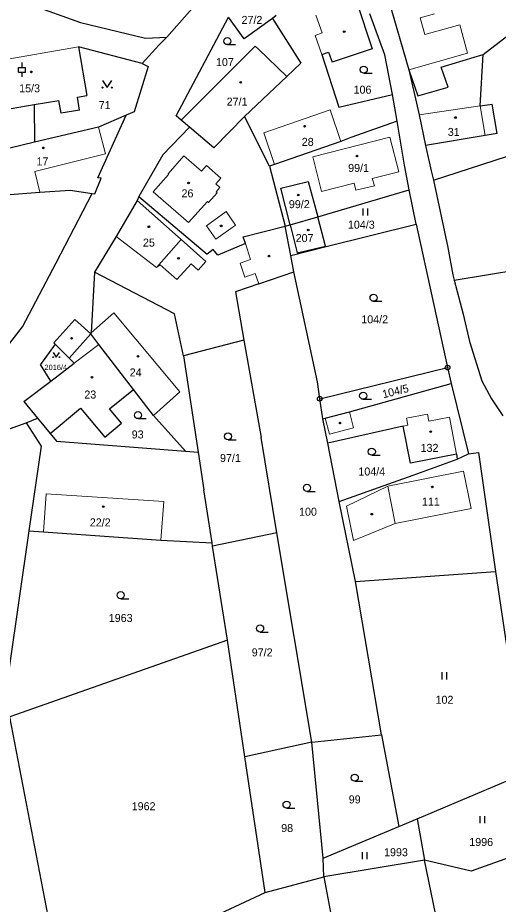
# Model space of a CAD drawing. Extents: x -820420 to -815896, y -1105820 to -1103643.
# Drawn here: x -817711.7 to -817609.6, y -1105107.9 to -1104919.6 of the extents above; entities that cross this region are included whole.
import ezdxf
from ezdxf.enums import TextEntityAlignment as Align

# ---------------------------------------------------------------- set-up
doc = ezdxf.new("R2010")
doc.units = 0
doc.header["$LTSCALE"] = 0.68
for name, color, linetype, lineweight in [('1', 7, 'Continuous', 25), ('3', 7, 'Continuous', 25), ('4', 7, 'Continuous', 13), ('5', 7, 'Continuous', 25), ('8', 7, 'Continuous', 25)]:
    doc.layers.add(name, color=color, linetype=linetype, lineweight=lineweight)
doc.layers.add('2', color=7, linetype='Continuous')

msp = doc.modelspace()

# ---------------------------------------------------------------- linework, layer by layer
at = {"layer": '1'}
for p, q in [((-817635.6, -1104906.5), (-817628.62, -1104930.65)), ((-817709.05, -1104916.79), (-817698.32, -1104920.58)), ((-817639.74, -1104916.15), (-817636.38, -1104926.16)), ((-817633.72, -1104927.48), (-817636.91, -1104918.76)), ((-817698.32, -1104920.58), (-817684.56, -1104923.92)), ((-817678.03, -1104940.45), (-817666.94, -1104919.46)), ((-817663.6, -1104924.08), (-817666.94, -1104919.46)), ((-817657.59, -1104919.72), (-817663.6, -1104924.08)), ((-817656.77, -1104919.13), (-817657.59, -1104919.72)), ((-817657.59, -1104919.72), (-817651.54, -1104929.22)), ((-817612.83, -1104927.36), (-817605.73, -1104921.95)), ((-817684.56, -1104923.92), (-817680.01, -1104923.68)), ((-817680.01, -1104923.68), (-817681.72, -1104925.42)), ((-817698.72, -1104925.76), (-817697, -1104936.12)), ((-817685.27, -1104929.28), (-817698.72, -1104925.76)), ((-817681.72, -1104925.42), (-817685.27, -1104929.28)), ((-817676.94, -1104941.36), (-817661.28, -1104925.6)), ((-817661.28, -1104925.6), (-817660.56, -1104926.25)), ((-817660.56, -1104926.25), (-817654.55, -1104932.07)), ((-817636.38, -1104926.16), (-817644.89, -1104929.02)), ((-817647.06, -1104927.4), (-817645.65, -1104926.9)), ((-817647.06, -1104927.4), (-817643.48, -1104938.56)), ((-817645.65, -1104926.9), (-817644.89, -1104929.02)), ((-817632.11, -1104935.86), (-817633.72, -1104927.48)), ((-817621.79, -1104930.11), (-817614.72, -1104927.93)), ((-817614.72, -1104927.93), (-817612.83, -1104927.36)), ((-817613.49, -1104938.27), (-817612.83, -1104927.36)), ((-817683.99, -1104929.96), (-817686.94, -1104939.54)), ((-817685.27, -1104929.28), (-817683.99, -1104929.96)), ((-817654.55, -1104932.07), (-817651.54, -1104929.22)), ((-817620.3, -1104934.31), (-817621.79, -1104930.11)), ((-817663.51, -1104940.56), (-817654.55, -1104932.07)), ((-817628.62, -1104930.65), (-817626.45, -1104940.24)), ((-817628.62, -1104930.65), (-817626.71, -1104936.18)), ((-817643.48, -1104938.56), (-817632.11, -1104935.86)), ((-817631.08, -1104941.53), (-817632.11, -1104935.86)), ((-817626.71, -1104936.18), (-817620.3, -1104934.31)), ((-817708.14, -1104938.03), (-817702.91, -1104937.13)), ((-817702.46, -1104939.87), (-817702.91, -1104937.13)), ((-817698.98, -1104936.46), (-817697, -1104936.12)), ((-817698.51, -1104939.18), (-817698.98, -1104936.46)), ((-817713.03, -1104938.87), (-817708.14, -1104938.03)), ((-817708.14, -1104938.03), (-817708.08, -1104946.04)), ((-817698.51, -1104939.18), (-817702.46, -1104939.87)), ((-817686.94, -1104939.54), (-817688.64, -1104940.27)), ((-817613.49, -1104938.27), (-817610.9, -1104937.92)), ((-817609.86, -1104944.17), (-817610.9, -1104937.92)), ((-817694.66, -1104953.6), (-817688.64, -1104940.27)), ((-817688.64, -1104940.27), (-817694.54, -1104942.82)), ((-817676.94, -1104941.36), (-817678.03, -1104940.45)), ((-817675.22, -1104942.8), (-817676.94, -1104941.36)), ((-817663.51, -1104940.56), (-817670.03, -1104947.24)), ((-817658.22, -1104951.1), (-817663.51, -1104940.56)), ((-817631.08, -1104941.53), (-817640.9, -1104945.04)), ((-817629.55, -1104950.9), (-817631.08, -1104941.53)), ((-817626.45, -1104940.24), (-817625.09, -1104946.72)), ((-817694.54, -1104942.82), (-817708.08, -1104946.04)), ((-817680.82, -1104948.67), (-817675.22, -1104942.8)), ((-817670.03, -1104947.24), (-817675.22, -1104942.8)), ((-817640.9, -1104945.04), (-817643.03, -1104945.89)), ((-817612.44, -1104944.57), (-817625.09, -1104946.72)), ((-817609.86, -1104944.17), (-817612.44, -1104944.57)), ((-817708.08, -1104946.04), (-817716.9, -1104948.13)), ((-817643.03, -1104945.89), (-817657.12, -1104950.74)), ((-817625.09, -1104946.72), (-817623.86, -1104952.1)), ((-817623.38, -1104954.07), (-817599.07, -1104946.21)), ((-817680.82, -1104948.67), (-817685.92, -1104957.55)), ((-817657.12, -1104950.74), (-817658.22, -1104951.1)), ((-817628.57, -1104956.14), (-817629.55, -1104950.9)), ((-817658.22, -1104951.1), (-817654.86, -1104963.88)), ((-817623.86, -1104952.1), (-817623.38, -1104954.07)), ((-817695.3, -1104957.01), (-817693.97, -1104953.69)), ((-817693.97, -1104953.69), (-817694.66, -1104953.6)), ((-817655.79, -1104955.8), (-817649.96, -1104954.4)), ((-817649.96, -1104954.4), (-817647.97, -1104961.85)), ((-817623.38, -1104954.07), (-817620.31, -1104968.4)), ((-817714.27, -1104957.17), (-817706.93, -1104956.61)), ((-817706.93, -1104956.61), (-817700.49, -1104956.19)), ((-817700.49, -1104956.19), (-817695.82, -1104956.94)), ((-817653.85, -1104963.58), (-817655.79, -1104955.8)), ((-817647.97, -1104961.85), (-817628.57, -1104956.14)), ((-817627.09, -1104963.44), (-817628.57, -1104956.14)), ((-817703.49, -1104971.65), (-817695.82, -1104956.94)), ((-817695.82, -1104956.94), (-817695.3, -1104957.01)), ((-817686.31, -1104958.41), (-817690.73, -1104966.04)), ((-817685.92, -1104957.55), (-817686.31, -1104958.41)), ((-817685.92, -1104957.55), (-817671.45, -1104969.83)), ((-817653.85, -1104963.58), (-817647.97, -1104961.85)), ((-817663.77, -1104966.09), (-817654.86, -1104963.88)), ((-817654.86, -1104963.88), (-817653.85, -1104963.58)), ((-817653.67, -1104970.08), (-817654.86, -1104963.88)), ((-817646.15, -1104968.19), (-817627.09, -1104963.44)), ((-817627.09, -1104963.44), (-817620.39, -1104993.9)), ((-817690.73, -1104966.04), (-817695.38, -1104973.64)), ((-817663.33, -1104967.57), (-817669.19, -1104969.98)), ((-817663.33, -1104967.57), (-817663.77, -1104966.09)), ((-817670.13, -1104968.8), (-817671.45, -1104969.83)), ((-817669.19, -1104969.98), (-817670.13, -1104968.8)), ((-817653.67, -1104970.08), (-817646.15, -1104968.19)), ((-817620.31, -1104968.4), (-817619.28, -1104974.19)), ((-817710.66, -1104985.25), (-817703.49, -1104971.65)), ((-817653.03, -1104973.58), (-817653.67, -1104970.08)), ((-817619.02, -1104975.33), (-817593.46, -1104971.11)), ((-817660.5, -1104976.07), (-817653.03, -1104973.58)), ((-817648.02, -1104996.92), (-817653.03, -1104973.58)), ((-817695.38, -1104973.64), (-817696.05, -1104986.5)), ((-817678.4, -1104982.48), (-817695.38, -1104973.64)), ((-817619.28, -1104974.19), (-817619.02, -1104975.33)), ((-817619.02, -1104975.33), (-817617.11, -1104982.53)), ((-817660.5, -1104976.07), (-817665.45, -1104977.81)), ((-817665.45, -1104977.81), (-817663.63, -1104988.09)), ((-817676.45, -1104991.42), (-817678.4, -1104982.48)), ((-817617.11, -1104982.53), (-817615.71, -1104988.33)), ((-817704, -1104988.65), (-817699.56, -1104983.68)), ((-817696.17, -1104986.71), (-817699.56, -1104983.68)), ((-817714.53, -1104990.23), (-817710.66, -1104985.25)), ((-817696.05, -1104986.5), (-817696.17, -1104986.71)), ((-817694.45, -1104989), (-817696.17, -1104986.71)), ((-817704, -1104988.65), (-817703.72, -1104988.93)), ((-817663.63, -1104988.09), (-817676.45, -1104991.42)), ((-817663.63, -1104988.09), (-817659.99, -1105008.72)), ((-817615.71, -1104988.33), (-817613.13, -1104996.68)), ((-817703.72, -1104988.93), (-817706.82, -1104993.26)), ((-817703.72, -1104988.93), (-817700.73, -1104991.87)), ((-817687.07, -1104998.54), (-817694.45, -1104989)), ((-817700.73, -1104991.87), (-817699.65, -1104992.96)), ((-817676.45, -1104991.42), (-817673.36, -1105011.84)), ((-817704.62, -1104996.77), (-817706.82, -1104993.26)), ((-817704.62, -1104996.77), (-817699.65, -1104992.96)), ((-817647.52, -1105000.5), (-817620.39, -1104993.9)), ((-817620.39, -1104993.9), (-817619.66, -1104997.26)), ((-817710.39, -1105001.11), (-817704.62, -1104996.77)), ((-817647.52, -1105000.5), (-817648.02, -1104996.92)), ((-817641.25, -1105003.28), (-817619.66, -1104997.26)), ((-817619.66, -1104997.26), (-817615.95, -1105012.22)), ((-817613.13, -1104996.68), (-817611.07, -1105000.53)), ((-817692.17, -1105002.66), (-817687.07, -1104998.54)), ((-817682.83, -1105004.06), (-817687.07, -1104998.54)), ((-817710.39, -1105001.11), (-817707.45, -1105004.65)), ((-817646.87, -1105004.76), (-817647.52, -1105000.5)), ((-817611.07, -1105000.53), (-817608.63, -1105004.11)), ((-817704.77, -1105007.88), (-817698.33, -1105002.54)), ((-817698.33, -1105002.54), (-817693.18, -1105008.68)), ((-817689.65, -1105005.71), (-817692.17, -1105002.66)), ((-817646.36, -1105004.63), (-817641.25, -1105003.28)), ((-817720.13, -1105009.32), (-817709.86, -1105005.6)), ((-817709.86, -1105005.6), (-817706.69, -1105010.56)), ((-817682.83, -1105004.06), (-817676.02, -1105011.65)), ((-817646.87, -1105004.76), (-817646.36, -1105004.63)), ((-817645.84, -1105009.94), (-817646.87, -1105004.76)), ((-817693.18, -1105008.68), (-817689.65, -1105005.71)), ((-817629.79, -1105006.31), (-817645.84, -1105009.94)), ((-817628.28, -1105014.17), (-817629.79, -1105006.31)), ((-817704.77, -1105007.88), (-817703.44, -1105009.49)), ((-817656.62, -1105029.01), (-817659.99, -1105008.72)), ((-817706.69, -1105010.56), (-817709.27, -1105028.56)), ((-817703.44, -1105009.49), (-817676.02, -1105011.65)), ((-817643.38, -1105022.33), (-817645.84, -1105009.94)), ((-817676.02, -1105011.65), (-817673.36, -1105011.84)), ((-817673.36, -1105011.84), (-817672.17, -1105019.85)), ((-817618.52, -1105012.29), (-817628.28, -1105014.17)), ((-817618.52, -1105012.29), (-817618.34, -1105013.32)), ((-817618.34, -1105013.32), (-817615.95, -1105012.22)), ((-817615.95, -1105012.22), (-817613.81, -1105011.94)), ((-817613.81, -1105011.94), (-817610.21, -1105037.23)), ((-817627.69, -1105016.77), (-817618.34, -1105013.32)), ((-817643.38, -1105022.33), (-817627.69, -1105016.77)), ((-817670.36, -1105031.11), (-817672.17, -1105019.85)), ((-817639.96, -1105039.33), (-817643.38, -1105022.33)), ((-817709.27, -1105028.56), (-817713.48, -1105057.68)), ((-817709.27, -1105028.56), (-817706.17, -1105028.76)), ((-817706.17, -1105028.76), (-817681.24, -1105030.52)), ((-817656.62, -1105029.01), (-817670.27, -1105031.86)), ((-817649.25, -1105073.45), (-817656.62, -1105029.01)), ((-817681.24, -1105030.52), (-817670.36, -1105031.11)), ((-817670.27, -1105031.86), (-817670.36, -1105031.11)), ((-817667.12, -1105051.76), (-817670.27, -1105031.86)), ((-817639.96, -1105039.33), (-817610.21, -1105037.23)), ((-817610.21, -1105037.23), (-817603.91, -1105080)), ((-817634.41, -1105071.9), (-817639.96, -1105039.33)), ((-817667.12, -1105051.76), (-817713.36, -1105068.05)), ((-817663.43, -1105076.57), (-817667.12, -1105051.76)), ((-817702.55, -1105124.25), (-817713.36, -1105068.05)), ((-817649.25, -1105073.45), (-817634.41, -1105071.9)), ((-817634.41, -1105071.9), (-817630.76, -1105091.4)), ((-817649.25, -1105073.45), (-817663.43, -1105076.57)), ((-817646.79, -1105098.13), (-817649.25, -1105073.45)), ((-817659.14, -1105105.4), (-817663.43, -1105076.57)), ((-817626.88, -1105089.77), (-817603.91, -1105080)), ((-817630.76, -1105091.4), (-817626.88, -1105089.77)), ((-817626.88, -1105089.77), (-817625.33, -1105098.49)), ((-817646.79, -1105098.13), (-817630.76, -1105091.4)), ((-817603.17, -1105096.45), (-817615.37, -1105100.88)), ((-817646.66, -1105102.08), (-817646.79, -1105098.13)), ((-817625.33, -1105098.49), (-817646.66, -1105102.08)), ((-817612.44, -1105160.35), (-817625.33, -1105098.49)), ((-817615.37, -1105100.88), (-817625.33, -1105098.49)), ((-817646.66, -1105102.08), (-817625.51, -1105215.45))]:
    msp.add_line(p, q, dxfattribs=at)
for points in [[(-817693.08, -1104912.51), (-817671.42, -1104913.92), (-817680.01, -1104923.68)], [(-817653.85, -1104963.58), (-817652.36, -1104969.52), (-817646.31, -1104968.07), (-817647.97, -1104961.85)], [(-817709.86, -1105005.6), (-817707.45, -1105004.65), (-817704.77, -1105007.88)], [(-817669.74, -1105110.38), (-817659.14, -1105105.4), (-817646.66, -1105102.08)]]:
    msp.add_lwpolyline(points, dxfattribs=at)
at = {"layer": '3'}
for p, q in [((-817667.153, -1104925.29), (-817665.403, -1104925.29)), ((-817711.481, -1104930.121), (-817709.979, -1104930.121)), ((-817711.481, -1104931.122), (-817711.481, -1104930.121)), ((-817710.73, -1104930.121), (-817710.73, -1104929.12)), ((-817709.979, -1104931.122), (-817709.979, -1104930.121)), ((-817711.481, -1104931.122), (-817709.979, -1104931.122)), ((-817710.73, -1104932.12), (-817710.73, -1104931.122)), ((-817638.183, -1104931.36), (-817636.433, -1104931.36)), ((-817638.331, -1104961.61), (-817638.331, -1104960.11)), ((-817637.33, -1104961.61), (-817637.33, -1104960.11)), ((-817636.113, -1104979.81), (-817634.363, -1104979.81)), ((-817638.313, -1105000.63), (-817636.563, -1105000.63)), ((-817686.113, -1105004.74), (-817684.363, -1105004.74)), ((-817667.013, -1105009.25), (-817665.263, -1105009.25)), ((-817636.483, -1105012.51), (-817634.733, -1105012.51)), ((-817650.243, -1105020.18), (-817648.493, -1105020.18)), ((-817689.793, -1105042.99), (-817688.043, -1105042.99)), ((-817660.203, -1105050.06), (-817658.453, -1105050.06)), ((-817621.561, -1105060.12), (-817621.561, -1105058.62)), ((-817620.56, -1105060.12), (-817620.56, -1105058.62)), ((-817640.103, -1105081.74), (-817638.353, -1105081.74)), ((-817654.583, -1105087.47), (-817652.833, -1105087.47)), ((-817613.501, -1105090.67), (-817613.501, -1105089.17)), ((-817612.5, -1105090.67), (-817612.5, -1105089.17)), ((-817638.461, -1105098.3), (-817638.461, -1105096.8)), ((-817637.46, -1105098.3), (-817637.46, -1105096.8))]:
    msp.add_line(p, q, dxfattribs=at)
for points in [[(-817693.69, -1104932.929), (-817692.69, -1104934.43), (-817691.69, -1104932.929)], [(-817704.13, -1104990.654), (-817703.46, -1104991.66), (-817702.79, -1104990.654)]]:
    msp.add_lwpolyline(points, dxfattribs=at)
for centre, radius in [((-817667.1529, -1104924.5398), 0.75), ((-817638.1829, -1104930.6098), 0.75), ((-817693.69, -1104934.4295), 0.1), ((-817691.69, -1104934.4295), 0.1), ((-817636.1129, -1104979.0598), 0.75), ((-817704.13, -1104991.6596), 0.067), ((-817702.79, -1104991.6596), 0.067), ((-817638.3129, -1104999.8798), 0.75), ((-817686.1129, -1105003.9898), 0.75), ((-817667.0129, -1105008.4998), 0.75), ((-817636.4829, -1105011.7598), 0.75), ((-817650.2429, -1105019.4298), 0.75), ((-817689.7929, -1105042.2398), 0.75), ((-817660.2029, -1105049.3098), 0.75), ((-817640.1029, -1105080.9898), 0.75), ((-817654.5829, -1105086.7198), 0.75)]:
    msp.add_circle(centre, radius, dxfattribs=at)
at = {"layer": '4'}
for p, q in [((-817648.4, -1104919), (-817647.04, -1104922.82)), ((-817623.18, -1104918.75), (-817626.2, -1104919.58)), ((-817626.2, -1104919.58), (-817625.22, -1104923.13)), ((-817625.22, -1104923.13), (-817617.82, -1104921.1)), ((-817617.82, -1104921.1), (-817616.16, -1104927.13)), ((-817647.04, -1104922.82), (-817648.5, -1104923.34)), ((-817648.5, -1104923.34), (-817647.06, -1104927.4)), ((-817698.72, -1104925.76), (-817724.12, -1104930.13)), ((-817616.16, -1104927.13), (-817628.62, -1104930.65)), ((-817626.45, -1104940.24), (-817613.49, -1104938.27)), ((-817613.49, -1104938.27), (-817612.44, -1104944.57)), ((-817693.05, -1104948.51), (-817694.54, -1104942.82)), ((-817657.12, -1104950.74), (-817659.42, -1104944.06)), ((-817632.68, -1104944.93), (-817649.02, -1104949.11)), ((-817630.77, -1104952.28), (-817632.68, -1104944.93)), ((-817679.74, -1104952.75), (-817676.36, -1104948.93)), ((-817676.36, -1104948.93), (-817672.66, -1104952.16)), ((-817649.02, -1104949.11), (-817647.13, -1104956.47)), ((-817672.66, -1104952.16), (-817671.6, -1104950.96)), ((-817671.6, -1104950.96), (-817668.51, -1104953.67)), ((-817682.9, -1104956.56), (-817679.62, -1104952.86)), ((-817679.62, -1104952.86), (-817679.74, -1104952.75)), ((-817668.51, -1104953.67), (-817669.57, -1104954.87)), ((-817675.39, -1104963.11), (-817682.9, -1104956.56)), ((-817669.57, -1104954.87), (-817668.73, -1104955.61)), ((-817668.73, -1104955.61), (-817669.54, -1104956.53)), ((-817669.54, -1104956.53), (-817669.31, -1104956.74)), ((-817686.31, -1104958.41), (-817676.95, -1104966.69)), ((-817669.31, -1104956.74), (-817671.18, -1104958.81)), ((-817671.39, -1104958.63), (-817675.39, -1104963.11)), ((-817671.18, -1104958.81), (-817671.39, -1104958.63)), ((-817671.59, -1104963.76), (-817667.38, -1104960.77)), ((-817667.38, -1104960.77), (-817665.4, -1104963.65)), ((-817669.61, -1104966.63), (-817671.59, -1104963.76)), ((-817665.4, -1104963.65), (-817669.61, -1104966.63)), ((-817682.19, -1104972.62), (-817690.73, -1104966.04)), ((-817676.95, -1104966.69), (-817682.19, -1104972.62)), ((-817676.95, -1104966.69), (-817671.7, -1104971.33)), ((-817662.21, -1104970.93), (-817663.33, -1104967.57)), ((-817671.7, -1104971.33), (-817673.33, -1104973.17)), ((-817664.45, -1104971.68), (-817662.21, -1104970.93)), ((-817663.46, -1104974.67), (-817664.45, -1104971.68)), ((-817681.43, -1104972.05), (-817682.19, -1104972.62)), ((-817677.86, -1104975.21), (-817681.43, -1104972.05)), ((-817674.86, -1104971.82), (-817677.86, -1104975.21)), ((-817673.33, -1104973.17), (-817674.86, -1104971.82)), ((-817661.22, -1104973.92), (-817663.46, -1104974.67)), ((-817660.5, -1104976.07), (-817661.22, -1104973.92)), ((-817696.05, -1104986.5), (-817691.24, -1104982.28)), ((-817691.24, -1104982.28), (-817677.26, -1104999.01)), ((-817700.73, -1104991.87), (-817696.17, -1104986.71)), ((-817699.65, -1104992.96), (-817694.45, -1104989)), ((-817677.26, -1104999.01), (-817682.83, -1105004.06)), ((-817641.25, -1105003.28), (-817640.36, -1105006.66)), ((-817645.47, -1105008.01), (-817646.36, -1105004.63)), ((-817629.09, -1105004.66), (-817624.64, -1105003.76)), ((-817628.81, -1105006.12), (-817629.09, -1105004.66)), ((-817624.64, -1105003.76), (-817624.36, -1105005.26)), ((-817624.36, -1105005.26), (-817620, -1105004.44)), ((-817620, -1105004.44), (-817618.52, -1105012.29)), ((-817640.36, -1105006.66), (-817645.47, -1105008.01)), ((-817629.79, -1105006.31), (-817628.81, -1105006.12)), ((-817633.1, -1105019.1), (-817616.98, -1105015.89)), ((-817616.98, -1105015.89), (-817615.39, -1105023.85)), ((-817706.17, -1105028.76), (-817705.6, -1105020.69)), ((-817705.6, -1105020.69), (-817680.64, -1105022.33)), ((-817641.82, -1105023.32), (-817633.1, -1105019.1)), ((-817631.52, -1105027.04), (-817633.1, -1105019.1)), ((-817681.24, -1105030.52), (-817680.64, -1105022.33)), ((-817640.4, -1105030.63), (-817641.82, -1105023.32)), ((-817615.39, -1105023.85), (-817631.52, -1105027.04)), ((-817631.52, -1105027.04), (-817640.4, -1105030.63))]:
    msp.add_line(p, q, dxfattribs=at)
for points in [[(-817659.42, -1104944.06), (-817645.34, -1104939.17), (-817643.03, -1104945.89)], [(-817693.05, -1104948.51), (-817708.06, -1104952.23), (-817706.93, -1104956.61)], [(-817647.13, -1104956.47), (-817640.22, -1104954.7), (-817639.87, -1104956.2), (-817635.94, -1104955.27), (-817636.42, -1104953.73), (-817630.77, -1104952.28)]]:
    msp.add_lwpolyline(points, dxfattribs=at)
at = {"layer": '5'}
for centre in [(-817642.3468, -1104922.5392), (-817708.7568, -1104931.0792), (-817664.3168, -1104933.2992), (-817618.7168, -1104940.7792), (-817650.7368, -1104942.6192), (-817706.2068, -1104947.2192), (-817639.6268, -1104948.9592), (-817675.3968, -1104954.6692), (-817652.0968, -1104957.2392), (-817683.8168, -1104963.9792), (-817668.4768, -1104963.7992), (-817649.9768, -1104964.6692), (-817677.5268, -1104970.6692), (-817658.3168, -1104970.2092), (-817700.2168, -1104987.6692), (-817686.1368, -1104991.4892), (-817695.8768, -1104995.9392), (-817643.2268, -1105005.6792), (-817623.9768, -1105007.4892), (-817623.6368, -1105019.2292), (-817693.4868, -1105023.4292), (-817636.4768, -1105025.0292)]:
    msp.add_circle(centre, 0.175, dxfattribs=at)
at = {"layer": '8'}
for centre, radius in [((-817620.39, -1104993.8999), 0.5), ((-817620.39, -1104993.8999), 0.0303), ((-817647.52, -1105000.4999), 0.5), ((-817647.52, -1105000.4999), 0.0303)]:
    msp.add_circle(centre, radius, dxfattribs=at)

# ---------------------------------------------------------------- texts
at = {"layer": '2'}
for s, height, p in [('27/2', 1.7, (-817661.929, -1104920.895)), ('107', 1.7, (-817667.669, -1104929.845)), ('15/3', 1.7, (-817709.139, -1104935.425)), ('106', 1.7, (-817638.459, -1104935.715)), ('71', 1.7, (-817693.199, -1104938.995)), ('27/1', 1.7, (-817665.089, -1104938.255)), ('31', 1.7, (-817619.089, -1104944.685)), ('28', 1.7, (-817650.089, -1104946.795)), ('17', 1.7, (-817706.409, -1104950.945)), ('99/1', 1.7, (-817639.289, -1104952.335)), ('26', 1.7, (-817675.619, -1104957.735)), ('99/2', 1.7, (-817651.879, -1104960.025)), ('104/3', 1.7, (-817638.71, -1104964.385)), ('25', 1.7, (-817683.809, -1104968.195)), ('104/2', 1.7, (-817635.87, -1104984.495)), ('2016/4', 1.139, (-817703.58, -1104994.414)), ('24', 1.7, (-817686.629, -1104995.775)), ('23', 1.7, (-817696.249, -1105000.465)), ('93', 1.7, (-817686.189, -1105008.945)), ('132', 1.7, (-817624.229, -1105011.795)), ('97/1', 1.7, (-817666.499, -1105013.945)), ('104/4', 1.7, (-817636.49, -1105016.815)), ('111', 1.7, (-817623.949, -1105023.225)), ('100', 1.7, (-817650.029, -1105025.355)), ('22/2', 1.7, (-817694.139, -1105027.625)), ('1963', 1.7, (-817689.8, -1105047.925)), ('97/2', 1.7, (-817659.759, -1105055.235)), ('102', 1.7, (-817621.049, -1105065.305)), ('1962', 1.7, (-817684.93, -1105087.915)), ('99', 1.7, (-817640.109, -1105086.465)), ('98', 1.7, (-817654.459, -1105092.545)), ('1996', 1.7, (-817613.26, -1105095.515)), ('1993', 1.7, (-817631.35, -1105097.685))]:
    msp.add_text(s, height=height, dxfattribs=at).set_placement(p, align=Align.CENTER)
msp.add_text('207', height=1.7, dxfattribs=at).set_placement((-817652.65, -1104967.235))
msp.add_text('104/5', height=1.7, rotation=14, dxfattribs=at).set_placement((-817631.2621, -1104999.7257), align=Align.CENTER)

doc.saveas('drawing.dxf')
